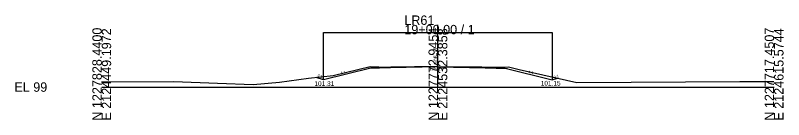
# Model space of a CAD drawing. Extents: x 2121193 to 2127979, y 1225108 to 1234639.
# Drawn here: x 2127750.9 to 2127979.4, y 1234107.5 to 1234138.6 of the extents above; entities that cross this region are included whole.
import ezdxf

# ---------------------------------------------------------------- set-up
doc = ezdxf.new("R2010")
doc.units = 0
for name, color, linetype in [('XS_CELL', 7, 'Continuous'), ('XS_M_DITCH', 7, 'Continuous'), ('XS_P_FINISHED_GRADE', 7, 'Continuous'), ('XS_P_FINISHED_GRADE_ELEV_TX', 7, 'Continuous'), ('XS_P_SUBGRADE_GRANULAR', 7, 'Continuous'), ('XS_P_SUBGRADE_PAVEMENT', 7, 'Continuous'), ('XS_P_TX_DCH', 7, 'Continuous'), ('XS_P_TX_FS_BS', 7, 'Continuous'), ('XS_X_GROUND', 7, 'Continuous'), ('XS_X_GROUND_TX', 7, 'Continuous')]:
    doc.layers.add(name, color=color, linetype=linetype)

msp = doc.modelspace()

# ---------------------------------------------------------------- linework, layer by layer
at = {"layer": 'XS_CELL'}
for p, q in [((2127876.61, 1234117.21), (2127876.61, 1234135.72)), ((2127776.61, 1234117.21), (2127876.61, 1234117.21)), ((2127876.61, 1234117.21), (2127976.61, 1234117.21))]:
    msp.add_line(p, q, dxfattribs=at)
at = {"layer": 'XS_M_DITCH'}
for p, q in [((2127842.61, 1234119.36), (2127842.61, 1234133.47)), ((2127842.61, 1234133.47), (2127910.61, 1234133.47)), ((2127910.61, 1234133.47), (2127910.61, 1234119.36))]:
    msp.add_line(p, q, dxfattribs=at)
at = {"layer": 'XS_P_FINISHED_GRADE'}
for p, q in [((2127856.61, 1234122.86), (2127842.61, 1234119.36)), ((2127862.61, 1234123.1), (2127856.61, 1234122.86)), ((2127876.61, 1234123.38), (2127862.61, 1234123.1)), ((2127876.61, 1234123.38), (2127890.61, 1234123.1)), ((2127890.61, 1234123.1), (2127896.61, 1234122.86)), ((2127896.61, 1234122.86), (2127910.61, 1234119.36)), ((2127842.61, 1234119.36), (2127840.4, 1234120.1)), ((2127910.61, 1234119.36), (2127912.17, 1234119.88))]:
    msp.add_line(p, q, dxfattribs=at)
at = {"layer": 'XS_P_SUBGRADE_GRANULAR'}
for p, q in [((2127862.54, 1234122.97), (2127856.02, 1234122.71)), ((2127890.68, 1234122.97), (2127897.2, 1234122.71))]:
    msp.add_line(p, q, dxfattribs=at)
at = {"layer": 'XS_P_SUBGRADE_PAVEMENT'}
for p, q in [((2127876.61, 1234123.25), (2127862.54, 1234122.97)), ((2127862.61, 1234123.1), (2127862.54, 1234122.97)), ((2127876.61, 1234123.25), (2127890.68, 1234122.97)), ((2127890.61, 1234123.1), (2127890.68, 1234122.97))]:
    msp.add_line(p, q, dxfattribs=at)
at = {"layer": 'XS_X_GROUND'}
for p, q in [((2127845.45, 1234120.67), (2127856.44, 1234123.38)), ((2127856.44, 1234123.38), (2127859.08, 1234123.21)), ((2127859.08, 1234123.21), (2127862.11, 1234123.01)), ((2127862.11, 1234123.01), (2127865.93, 1234123.11)), ((2127865.93, 1234123.11), (2127876.61, 1234123.38)), ((2127876.61, 1234123.38), (2127889.7, 1234123.28)), ((2127889.7, 1234123.28), (2127896.1, 1234123.15)), ((2127896.1, 1234123.15), (2127897.63, 1234123.2)), ((2127897.63, 1234123.2), (2127900.73, 1234122.45)), ((2127900.73, 1234122.45), (2127917.97, 1234118.58)), ((2127829.48, 1234118.68), (2127838.15, 1234119.84)), ((2127838.15, 1234119.84), (2127845.45, 1234120.67)), ((2127776.51, 1234118.78), (2127798.06, 1234118.84)), ((2127798.06, 1234118.84), (2127811.09, 1234118.39)), ((2127811.09, 1234118.39), (2127821.68, 1234117.94)), ((2127821.68, 1234117.94), (2127829.48, 1234118.68)), ((2127917.97, 1234118.58), (2127966.45, 1234118.89)), ((2127966.45, 1234118.89), (2127976.51, 1234118.9))]:
    msp.add_line(p, q, dxfattribs=at)

# ---------------------------------------------------------------- texts
at = {"layer": 'XS_CELL'}
for s, p in [('LR61', (2127866.61, 1234135.72)), ('19+00.00 / 1', (2127866.61, 1234132.92)), ('EL 99', (2127750.61, 1234115.81))]:
    msp.add_text(s, height=2.8, dxfattribs=at).set_placement(p)
for s, p in [('N 1227828.4400', (2127776.61, 1234107.21)), ('E 2124449.1972', (2127779.41, 1234107.21)), ('N 1227772.9454', (2127876.61, 1234107.21)), ('E 2124532.3858', (2127879.41, 1234107.21)), ('N 1227717.4507', (2127976.61, 1234107.21)), ('E 2124615.5744', (2127979.41, 1234107.21))]:
    msp.add_text(s, height=2.8, rotation=90, dxfattribs=at).set_placement(p)
at = {"layer": 'XS_P_FINISHED_GRADE_ELEV_TX'}
msp.add_text(' 105.17', height=1.25, rotation=90, dxfattribs=at).set_placement((2127876.61, 1234123.37))
at = {"layer": 'XS_P_TX_DCH'}
for s, p in [('101.31', (2127839.87, 1234117.54)), ('101.15', (2127907.19, 1234117.66))]:
    msp.add_text(s, height=1.4, dxfattribs=at).set_placement(p)
at = {"layer": 'XS_P_TX_FS_BS'}
for s, rotation, p in [('4:1', 14.0362, (2127847.74, 1234120.96)), ('4:1', 345.9638, (2127903.38, 1234121.42)), ('3:1', 341.5651, (2127840.69, 1234120.4)), ('3:1', 18.4349, (2127911.21, 1234119.7))]:
    msp.add_text(s, height=0.8, rotation=rotation, dxfattribs=at).set_placement(p)
at = {"layer": 'XS_X_GROUND_TX'}
msp.add_text('105.17', height=1, dxfattribs=at).set_placement((2127873.95, 1234122.21))

doc.saveas('drawing.dxf')
